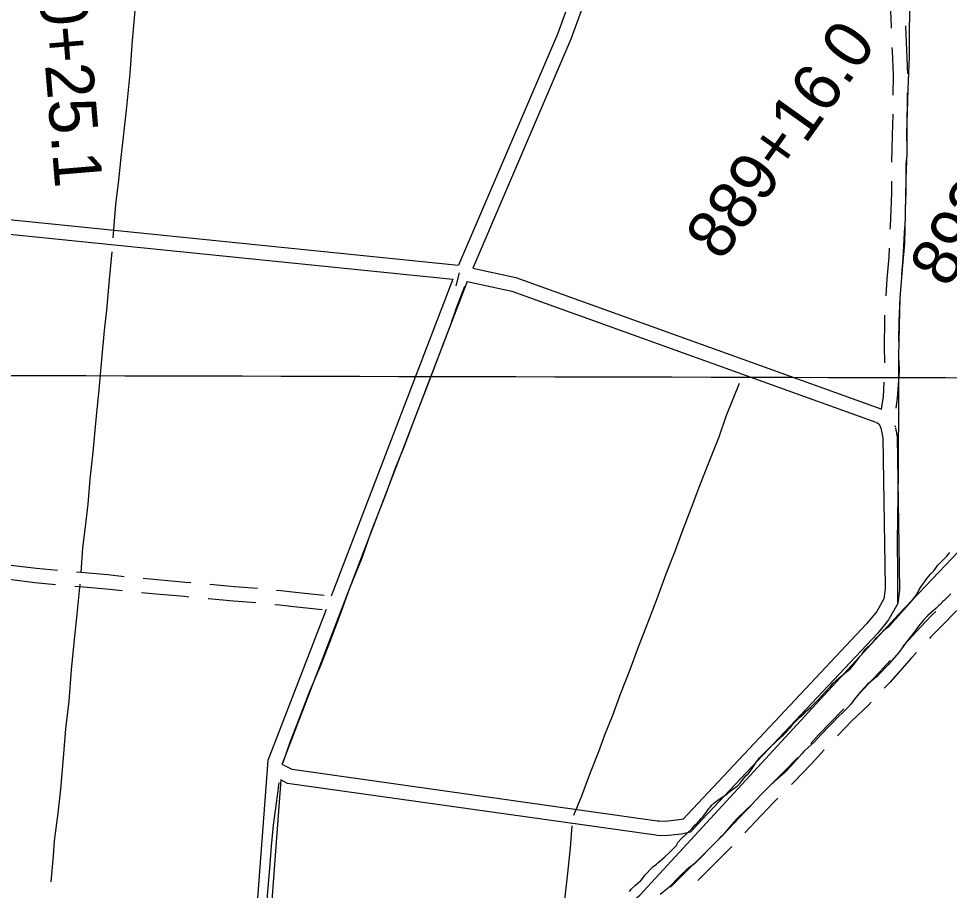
# Model space of a CAD drawing. Extents: x 3161514 to 3199414, y 831166 to 856601.
# Drawn here: x 3186690 to 3188637, y 847621 to 849442 of the extents above; entities that cross this region are included whole.
import ezdxf

# ---------------------------------------------------------------- set-up
doc = ezdxf.new("R2010")
doc.units = 0
for name, color, linetype in [('V-GRID-MAJR', 7, 'Continuous'), ('V-ROAD-CNTR', 7, 'Continuous'), ('V-SITE-VEGE', 7, 'Continuous'), ('V-SURV-IDEN', 7, 'Continuous'), ('V-TOPO-SHOR', 7, 'Continuous')]:
    doc.layers.add(name, color=color, linetype=linetype)

msp = doc.modelspace()

# ---------------------------------------------------------------- linework, layer by layer
at = {"layer": 'V-GRID-MAJR'}
msp.add_spline([(3165741.648, 848757.608), (3170973.071, 848741.248), (3176204.497, 848725.65), (3181435.9250000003, 848710.812), (3186667.355, 848696.736), (3191898.788, 848683.42), (3197130.222, 848670.865), (3197130.223, 848670.865)], degree=3, dxfattribs=at)
at = {"layer": 'V-ROAD-CNTR'}
msp.add_line((3187611.2970000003, 848910.909), (3187604.954, 848884.084), dxfattribs=at)
for points in [[(3187899.3676877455, 849548.9017655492), (3187844.8882733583, 849399.095174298), (3187640.0156831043, 848921.079130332)], [(3188458.8966407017, 849483.0913640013), (3188477.066124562, 849481.4935287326), (3188500.817333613, 849474.7360088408), (3188509.1458262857, 849467.1084731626), (3188513.1450737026, 849458.9066575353), (3188514.6860891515, 849425.1350981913), (3188514.7948283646, 849422.2957591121)], [(3187833.6983398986, 849456.1046465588), (3187816.98232917, 849410.13915221), (3187609.908743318, 848926.9861185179)], [(3188544.6316498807, 849427.0122446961), (3188544.659910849, 849426.3929018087), (3188546.59759409, 849375.797172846), (3188548.8731557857, 849327.1080158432)], [(3188516.3256009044, 849382.3250606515), (3188516.6244059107, 849374.5228271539), (3188518.980779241, 849324.104580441), (3188518.5973377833, 849282.3927877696)], [(3188548.6419920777, 849287.1125152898), (3188548.439689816, 849265.1055313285), (3188547.1576286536, 849197.6510851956), (3188546.90868348, 849187.1287782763)], [(3188518.002679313, 849242.3977025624), (3188517.1643713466, 849198.2909148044), (3188515.8425814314, 849142.422070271)], [(3188545.962608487, 849147.1404895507), (3188545.6798403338, 849135.1885675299), (3188545.3020264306, 849077.3900554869), (3188544.084961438, 849047.1714318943)], [(3188515.4650309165, 849102.424765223), (3188515.3059735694, 849078.0919445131), (3188512.485389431, 849008.0593900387), (3188512.238256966, 849002.4915801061)], [(3186177.48060818, 849073.0608263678), (3186182.1755987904, 849071.942828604), (3186945.066073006, 848994.486983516)], [(3186172.081618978, 849043.506885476), (3186177.163608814, 849042.2968878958), (3186939.28408457, 848964.92004265)], [(3188542.4753442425, 849007.2060919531), (3188542.458610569, 849006.7906099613), (3188539.5777629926, 848941.8860991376), (3188536.642733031, 848907.3960593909)], [(3186945.066073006, 848994.486983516), (3187609.908743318, 848926.9861185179)], [(3186939.28408457, 848964.92004265), (3187598.4807661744, 848897.9921765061)], [(3188510.4645698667, 848962.5310162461), (3188509.6342370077, 848943.8239008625), (3188505.8063584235, 848898.8418440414), (3188503.403687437, 848862.7959943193)], [(3187640.0156831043, 848921.079130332), (3187730.023503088, 848901.659169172), (3188495.1859727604, 848626.0767203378)], [(3187628.641705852, 848892.8431868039), (3187241.3034805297, 847884.934202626), (3187241.2204806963, 847883.82220485)], [(3187598.4807661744, 848897.9921765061), (3187343.884973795, 848235.4962213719)], [(3187628.641705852, 848892.8431868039), (3187721.739519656, 848872.75522698), (3188482.66099781, 848598.699775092)], [(3188533.783958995, 848867.5022518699), (3188533.245282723, 848859.4208108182), (3188530.582574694, 848809.7327947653), (3188530.118231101, 848767.5980322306)], [(3188501.242743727, 848822.8552678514), (3188500.591425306, 848810.7012052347), (3188500.00702991, 848757.672883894), (3188500.836204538, 848722.8893399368)], [(3188530.7322422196, 848727.6080387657), (3188531.270354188, 848705.0344569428), (3188527.740395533, 848649.493708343), (3188524.3878588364, 848627.9872380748)], [(3188499.805594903, 848682.9401591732), (3188497.887604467, 848652.762291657), (3188493.728190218, 848626.0797145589)], [(3188483.30599652, 848598.4677755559), (3188485.821991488, 848597.5617773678), (3188489.1039849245, 848595.267781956), (3188492.671977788, 848589.1267942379), (3188494.0959749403, 848583.111806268)], [(3188494.0959749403, 848583.111806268), (3188494.706973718, 848580.532811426), (3188497.444968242, 848565.616841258), (3188502.237958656, 848255.8554607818)], [(3188522.766105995, 848592.2304545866), (3188523.6459158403, 848588.5147954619)], [(3188524.074914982, 848586.70079909), (3188527.402908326, 848568.5788353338), (3188532.33589846, 848249.78647292)], [(3186672.1537041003, 848300.7318629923), (3186674.42479368, 848300.469734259), (3186727.576880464, 848293.5607201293), (3186771.518712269, 848289.6821613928)], [(3186811.3732332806, 848286.2894979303), (3186820.8256828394, 848285.4881671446), (3186876.750846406, 848280.7274891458), (3186910.907560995, 848276.7646264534)], [(3186668.5137577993, 848270.9528200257), (3186670.77120632, 848270.6922657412), (3186724.3231195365, 848263.7312798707), (3186767.8770697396, 848259.8869577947)], [(3186950.7223914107, 848272.9525289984), (3186980.3961143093, 848270.3416541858), (3187040.3296974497, 848264.9195351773), (3187050.317415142, 848263.9644577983)], [(3186807.7312700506, 848256.4906362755), (3186818.286317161, 848255.5958328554), (3186873.749153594, 848250.8745108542), (3186907.267561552, 848246.9857045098)], [(3187090.135747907, 848260.1568222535), (3187090.283478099, 848260.1426955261), (3187142.087874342, 848255.394582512), (3187189.7779942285, 848251.7386827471)], [(3187229.606573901, 848248.0483494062), (3187238.6506059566, 848247.1929733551), (3187269.4818784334, 848243.8630673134), (3187315.103180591, 848238.6373327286), (3187329.0152921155, 848237.2380002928)], [(3188502.237958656, 848255.8554607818), (3188502.3309584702, 848249.8694727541), (3188499.741963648, 848229.5235134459), (3188484.6779937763, 848203.2925659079), (3188480.994001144, 848198.773574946)], [(3188532.336898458, 848249.7544729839), (3188532.36089841, 848248.199476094), (3188528.743905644, 848219.785532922), (3188510.277942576, 848187.6295972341)], [(3186947.080703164, 848243.1570475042), (3186977.729885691, 848240.4603458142), (3187037.55030255, 848235.0484648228), (3187046.6763517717, 848234.1757846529)], [(3187086.494684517, 848230.3681491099), (3187087.486521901, 848230.2733044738), (3187139.572125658, 848225.4994174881), (3187186.1352081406, 848221.9299158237)], [(3187333.1546985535, 848207.5744561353), (3187211.719539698, 847891.5821893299), (3187179.59860394, 847464.9120426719), (3187175.6076119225, 847449.9990724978), (3187160.225642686, 847433.1231062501), (3187140.624681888, 847421.6061292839), (3187113.595735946, 847414.3041438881), (3187064.9228332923, 847414.4911435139), (3186909.78914356, 847411.1221502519), (3186857.9212472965, 847396.136180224), (3186812.546338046, 847381.5322094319), (3186538.582885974, 847242.6484872), (3186450.9920611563, 847193.1055862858), (3186359.662243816, 847135.267701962), (3186313.8103355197, 847105.28876192)], [(3187225.9654386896, 848218.2588453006), (3187235.6273940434, 848217.345026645), (3187266.164121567, 848214.0469326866), (3187311.894819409, 848208.8086672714), (3187325.3745490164, 848207.452825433)], [(3188665.2470907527, 848217.5004004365), (3188647.384729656, 848200.2797016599), (3188622.1171110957, 848175.0577480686), (3188597.297339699, 848149.3981427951), (3188594.7120180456, 848146.6305248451)], [(3188480.994001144, 848198.773574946), (3188463.52603608, 848177.348617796), (3188100.190762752, 847791.2603899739)], [(3188510.277942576, 848187.6295972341), (3188509.47594418, 848186.232600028), (3188486.103990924, 848157.5646573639), (3188120.553722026, 847769.1224342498)], [(3188608.1152738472, 848203.4693022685), (3188600.7368889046, 848196.1042519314), (3188575.552660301, 848170.0678572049), (3188550.8418484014, 848143.6146356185), (3188539.312929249, 848130.9160619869)], [(3188567.491197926, 848117.3226364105), (3188557.5459841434, 848106.3684413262), (3188511.865687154, 848055.2597210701), (3188500.4757582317, 848043.1073221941)], [(3188512.622295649, 848101.1241577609), (3188489.7343128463, 848075.51627893), (3188446.1442712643, 848029.0082123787), (3188444.7632704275, 848027.6880669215)], [(3188473.1222842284, 848013.922739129), (3188467.469728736, 848007.8917876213), (3188432.572093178, 847974.5319562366), (3188402.4854605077, 847943.1766666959)], [(3188415.8498505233, 848000.048749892), (3188411.3739068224, 847995.7700437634), (3188362.9767671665, 847945.332151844), (3188346.7670144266, 847927.7611620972)], [(3188319.5112483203, 847898.4865562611), (3188289.49625176, 847867.2686166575), (3188249.378385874, 847827.212881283)], [(3188374.9983384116, 847914.1195583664), (3188347.502135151, 847884.3143223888), (3188310.90974824, 847846.2553833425), (3188306.2025721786, 847841.5554972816)], [(3188029.88190337, 847765.2304420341), (3188025.6019119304, 847765.464441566), (3187262.1394388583, 847872.8462268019), (3187241.2204806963, 847883.82220485)], [(3187238.7664856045, 847851.2332700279), (3187209.302544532, 847459.864052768), (3187202.6995577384, 847435.1871021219), (3187179.337604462, 847409.5571533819), (3187152.3446584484, 847393.696185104), (3187117.519728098, 847384.2882039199), (3187065.190832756, 847384.4892035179), (3186914.355134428, 847381.214210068), (3186866.6832297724, 847367.4402376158), (3186823.996315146, 847353.7022650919), (3186552.756857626, 847216.1985400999), (3186466.4120303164, 847167.361637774), (3186375.896211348, 847110.0397524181), (3186330.2283026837, 847080.17881214)], [(3188025.754911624, 847735.4105016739), (3188022.6879177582, 847735.578501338), (3187252.809457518, 847843.864284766), (3187238.767485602, 847851.2302700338)], [(3188221.8461005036, 847798.1971164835), (3188209.3549325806, 847785.0000117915), (3188162.045363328, 847734.9759590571), (3188152.8585876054, 847725.8135226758)], [(3188277.897360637, 847813.2941220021), (3188269.6263175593, 847805.0358882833), (3188231.1470674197, 847764.3819882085), (3188208.92961525, 847740.8897641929)], [(3188100.190762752, 847791.2603899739), (3188088.8137855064, 847779.1704141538), (3188079.64680384, 847769.468433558), (3188071.2748205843, 847767.7594369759), (3188042.284878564, 847764.550443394), (3188029.88190337, 847765.2304420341)], [(3188120.553722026, 847769.1224342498), (3188110.6397418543, 847758.588455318), (3188094.940773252, 847741.97248855), (3188075.9348112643, 847738.091496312), (3188043.120876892, 847734.4605035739), (3188025.754911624, 847735.4105016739)], [(3188181.38165705, 847711.8907812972), (3188145.245990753, 847675.8508524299), (3188110.464215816, 847641.3895389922)], [(3188124.5375353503, 847697.5675038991), (3188124.096009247, 847697.1271475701), (3188085.5297230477, 847658.9161914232), (3188053.175808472, 847627.5170115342)]]:
    msp.add_lwpolyline(points, dxfattribs=at)
at = {"layer": 'V-SITE-VEGE'}
for points in [[(3188140.365, 847799.336), (3188144.076, 847802.621), (3188147.791, 847805.439), (3188161.486, 847815.54), (3188167.294, 847819.069), (3188172.4020000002, 847822.829), (3188174.951, 847825.174), (3188180.753, 847829.634), (3188191.667, 847837.388), (3188193.289, 847838.797), (3188198.157, 847843.718), (3188203.253, 847849.809), (3188211.815, 847860.5800000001), (3188215.524, 847864.332), (3188219.923, 847869.484), (3188224.323, 847875.104), (3188233.3340000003, 847888.908), (3188239.812, 847897.802), (3188255.344, 847913.508), (3188257.662, 847915.386), (3188275.975, 847933.206), (3188281.775, 847938.367), (3188285.251, 847941.881), (3188288.73, 847944.933), (3188294.989, 847951.261), (3188302.403, 847959.461), (3188304.025, 847961.104), (3188306.572, 847963.911), (3188310.046, 847968.3640000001), (3188312.593, 847971.176), (3188323.024, 847981.723), (3188332.764, 847990.402), (3188336.008, 847993.685), (3188345.982, 848002.832), (3188355.255, 848011.742), (3188361.2830000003, 848017.837), (3188375.879, 848034.0040000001), (3188387.691, 848046.892), (3188393.717, 848053.221), (3188405.544, 848064.009), (3188429.6750000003, 848084.193), (3188434.075, 848089.112), (3188444.257, 848102.457), (3188445.879, 848104.0970000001), (3188450.276, 848109.7170000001), (3188453.285, 848113.696), (3188460.219, 848123.76), (3188462.538, 848126.336), (3188472.739, 848135.952), (3188480.619, 848143.922), (3188485.019, 848148.8420000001), (3188487.3370000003, 848151.652), (3188491.2770000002, 848155.404), (3188497.305, 848161.498), (3188500.315, 848165.013), (3188502.6350000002, 848166.657), (3188505.654, 848169.0040000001), (3188511.917, 848173.936), (3188552.6890000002, 848219.623), (3188558.943, 848226.649), (3188564.497, 848233.674), (3188565.6520000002, 848235.546), (3188568.8880000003, 848240.459), (3188572.81, 848247.709), (3188576.042, 848253.554), (3188581.133, 848260.343), (3188585.528, 848265.963), (3188588.301, 848270.1730000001), (3188590.611, 848273.915), (3188592.928, 848276.7270000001), (3188598.023, 848282.117), (3188603.8170000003, 848288.444), (3188607.286, 848293.359), (3188612.376, 848300.148), (3188626.286, 848313.745), (3188630.916, 848319.133), (3188634.16, 848322.647), (3188637.633, 848326.862)], [(3188639.755, 848239.927), (3188635.114, 848236.171), (3188630.248, 848231.483), (3188626.308, 848227.03), (3188622.595, 848223.9770000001), (3188617.2660000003, 848218.121), (3188614.95, 848216.243), (3188610.307, 848212.018), (3188607.9930000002, 848209.444), (3188597.089, 848199.8250000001), (3188591.756, 848194.899), (3188582.718, 848185.5260000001), (3188575.307, 848177.0920000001), (3188572.069, 848172.41), (3188568.597, 848167.962), (3188558.19, 848153.683), (3188544.529, 848137.056), (3188536.438, 848125.122), (3188532.737, 848120.207), (3188530.6520000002, 848117.63), (3188512.359, 848096.081), (3188508.421, 848091.631), (3188502.162, 848085.534), (3188496.137, 848078.9720000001)], [(3188496.137, 848078.9720000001), (3188492.43, 848075.2220000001), (3188485.9420000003, 848068.192), (3188479.448, 848062.328), (3188470.861, 848055.7540000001), (3188468.77, 848054.574), (3188465.984, 848052.229), (3188460.426, 848045.903), (3188450.694, 848035.36), (3188437.9620000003, 848019.902), (3188431.023, 848010.305), (3188425.696, 848004.214), (3188415.727, 847994.601), (3188402.515, 847981.473), (3188393.244, 847971.8640000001), (3188383.972, 847962.486), (3188369.8370000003, 847947.4890000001), (3188360.105, 847937.408), (3188353.617, 847930.38), (3188335.295, 847913.723), (3188332.2830000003, 847910.6780000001), (3188328.113, 847905.761), (3188305.182, 847879.988), (3188293.592, 847868.268), (3188286.866, 847862.169), (3188277.122, 847853.954), (3188261.8170000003, 847839.883), (3188253.705, 847831.4450000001), (3188241.653, 847819.4890000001), (3188221.955, 847798.863), (3188212.45, 847789.256), (3188207.816, 847784.797), (3188195.061, 847773.071), (3188192.046, 847770.023), (3188180.929, 847757.373), (3188166.342, 847740.04), (3188161.4760000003, 847734.654), (3188158.926, 847732.307), (3188150.812, 847724.336), (3188145.485, 847718.4770000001), (3188137.137, 847710.273), (3188132.271, 847705.116), (3188119.758, 847692.224), (3188105.616, 847678.158), (3188103.296, 847676.28), (3188091.921, 847667.826), (3188086.1210000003, 847662.8960000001), (3188077.54, 847655.157), (3188068.5, 847646.246), (3188054.83, 847631.718), (3188050.4250000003, 847627.263), (3188045.784, 847623.274), (3188031.63, 847612.006)], [(3187967.9560000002, 847618.4060000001), (3187970.037, 847621.213), (3187971.423, 847623.321), (3187980.238, 847631.296), (3187991.373, 847641.149), (3187995.309, 847645.832), (3187999.933, 847652.153), (3188016.852, 847669.4990000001), (3188019.6350000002, 847672.0800000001), (3188024.278, 847675.6), (3188027.758, 847678.652), (3188040.285, 847688.98), (3188052.809, 847700.7050000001), (3188057.9080000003, 847705.63), (3188062.307, 847711.014), (3188066.713, 847715.235), (3188067.63, 847717.805), (3188068.781, 847720.376), (3188075.961, 847728.3420000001), (3188098.686, 847749.916), (3188104.474, 847756.709), (3188109.575, 847761.633), (3188113.2800000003, 847766.085), (3188117.915, 847770.7710000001), (3188120.927, 847774.052), (3188125.785, 847780.372), (3188134.108, 847792.541), (3188136.1950000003, 847794.65), (3188140.365, 847799.336)]]:
    msp.add_lwpolyline(points, dxfattribs=at)
at = {"layer": 'V-TOPO-SHOR'}
for points in [[(3186954.747, 849669.279), (3186946.651, 849605.291), (3186940.569, 849540.183), (3186933.833, 849466.795), (3186928.037, 849396.723), (3186923.281, 849327.525)], [(3188548.521, 849223.206), (3188550.731, 849295.699), (3188553.498, 849362.272), (3188553.258, 849420.986), (3188554.974, 849503.667), (3188602.553, 849501.318)], [(3186923.281, 849327.525), (3186915.0810000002, 849251.3420000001), (3186909.8710000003, 849201.481), (3186904.049, 849151.969), (3186898.998, 849104.463), (3186893.356, 849053.904), (3186887.558, 848984.2660000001)], [(3188530.98, 848595.4), (3188531.0700000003, 848664.5260000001), (3188530.845, 848736.22), (3188532.231, 848799.997), (3188533.558, 848859.1560000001), (3188538.367, 848918.7710000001), (3188543.382, 848972.285), (3188544.519, 849034.231), (3188546.465, 849107.2440000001), (3188548.505, 849163.446), (3188548.521, 849223.206)], [(3187811.7060000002, 847458.936), (3187989.6350432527, 847610.7275198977), (3188530.656807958, 848197.7184541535), (3188753.430475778, 848431.1003918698), (3189043.389852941, 848685.6988693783), (3189351.029679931, 849021.6274160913)], [(3186885.457, 848954.724), (3186879.593, 848896.845), (3186874.287, 848832.962), (3186869.034, 848790.769), (3186863.881, 848730.107), (3186857.9620000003, 848666.828), (3186851.773, 848604.681), (3186845.6210000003, 848536.262)], [(3187540.7800000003, 848662.454), (3187560.187, 848713.262), (3187576.4930000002, 848757.522), (3187594.272, 848802.92), (3187606.0130000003, 848837.832), (3187623.708, 848883.056)], [(3187986.302, 848129.564), (3188007.171, 848183.1680000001), (3188025.378, 848230.399), (3188044.256, 848281.902), (3188063.071, 848329.309), (3188077.057, 848367.806), (3188096.548, 848418.877), (3188115.099, 848466.632), (3188134.163, 848516.046), (3188154.957, 848568.256), (3188169.612, 848611.546), (3188198.061, 848680.787)], [(3187427.8510000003, 848369.729), (3187458.082, 848447.952), (3187477.818, 848501.638), (3187497.844, 848550.969), (3187519.823, 848609.023), (3187540.7800000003, 848662.454)], [(3188528.528, 848221.9230000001), (3188528.608, 848285.777), (3188528.182, 848346.6680000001), (3188529.1, 848401.035), (3188529.223, 848441.632), (3188530.31, 848496.432), (3188530.126, 848561.157), (3188530.98, 848595.4)], [(3186845.6210000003, 848536.262), (3186839.664, 848479.6900000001), (3186834.986, 848427.831), (3186828.748, 848374.6560000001), (3186823.91, 848336.037), (3186820.537, 848284.62)], [(3187243.494, 847888.088), (3187258.668, 847932.339), (3187277.653, 847980.359), (3187298.514, 848035.706), (3187323.284, 848092.905), (3187344.4960000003, 848148.2540000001), (3187365.019, 848201.768), (3187382.08, 848250.91), (3187408.553, 848315.522), (3187427.8510000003, 848369.729)], [(3186818.235, 848260.128), (3186811.9620000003, 848197.5430000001), (3186805.759, 848138.01), (3186800.5, 848081.268), (3186795.111, 848016.25), (3186788.73, 847957.8470000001), (3186783.403, 847897.534)], [(3187851.052, 847777.91), (3187867.815, 847817.9890000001), (3187885.073, 847863.211), (3187903.45, 847911.0530000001), (3187915.89, 847945.533), (3187932.822, 847986.659), (3187949.9050000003, 848032.3150000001), (3187969.228, 848082.427), (3187986.302, 848129.564)], [(3186783.403, 847897.534), (3186777.667, 847832.34), (3186772.112, 847781.609), (3186765.028, 847723.724), (3186762.673, 847692.959), (3186757.926, 847638.224)], [(3187205.676, 847514.152), (3187208.322, 847570.794), (3187211.1950000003, 847618.113), (3187215.457, 847666.224), (3187219.0330000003, 847712.589), (3187223.406, 847756.6950000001), (3187232.036, 847818.157), (3187235.1920000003, 847845.965)], [(3187811.7060000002, 847458.936), (3187817.971, 847491.8150000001), (3187824.684, 847537.762), (3187831.287, 847587.976), (3187838.662, 847656.142), (3187844.6380000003, 847709.402), (3187848.125, 847755.593)]]:
    msp.add_lwpolyline(points, dxfattribs=at)

# ---------------------------------------------------------------- texts
at = {"layer": 'V-SURV-IDEN'}
for s, height, rotation, p in [('870+25.1', 100.00000000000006, 274.76213906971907, (3186720.564197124, 849646.063853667)), ('889+16.0', 100.00000000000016, 54.46366371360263, (3188159.8919769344, 848932.9409987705)), ('892+91.4', 100.00000000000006, 59.51506928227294, (3188634.0695887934, 848876.2215712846))]:
    msp.add_text(s, height=height, rotation=rotation, dxfattribs=at).set_placement(p)

doc.saveas('drawing.dxf')
